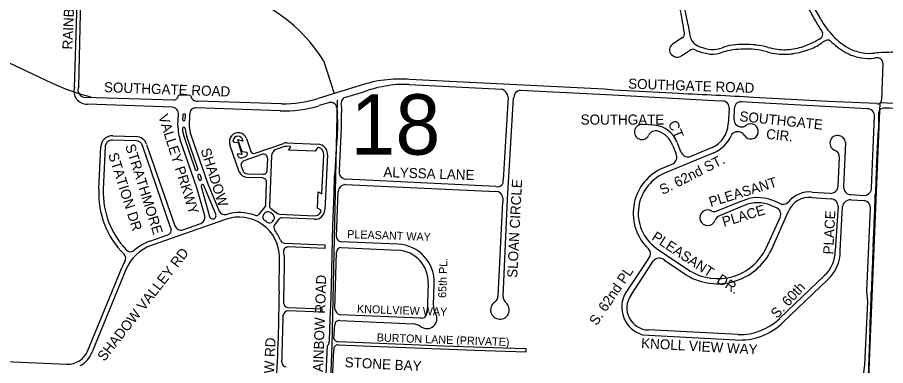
# Model space of a CAD drawing. Extents: x 0 to 712119, y 0 to 761125.
# Drawn here: x 660107 to 664425, y 718772 to 720502 of the extents above; entities that cross this region are included whole.
import ezdxf

# ---------------------------------------------------------------- set-up
doc = ezdxf.new("R2010")
doc.units = 0
for name, color, linetype in [('ISLANDS', 7, 'Continuous'), ('PAVED ROADS', 7, 'Continuous'), ('Priority 12', 7, 'Continuous'), ('Priority 16', 7, 'Continuous'), ('Priority 18', 7, 'Continuous'), ('street names', 7, 'Continuous')]:
    doc.layers.add(name, color=color, linetype=linetype)

msp = doc.modelspace()

# ---------------------------------------------------------------- linework, layer by layer
at = {"layer": 'ISLANDS'}
msp.add_lwpolyline([(664310.7, 717427.5), (664952, 717398.1), (665618, 717367.5), (665668.3, 718692.6), (665718.7, 720018.1), (664396.1, 720078.2), (664341, 718753), (664286, 717428.7)], close=True, dxfattribs=at)
at = {"layer": 'PAVED ROADS'}
for points in [[(660390.6, 720154.9), (660390.6, 720154.9), (660390.6, 720154.9), (660392.6, 720201.8), (660408.1, 720691.1), (660418.5, 721053.5), (660435.5, 721371.5), (660449, 721718), (660460.5, 721947)], [(660412.4, 720158.9), (660421.8, 720522), (660434.5, 720906.5), (660443.5, 721196), (660460.5, 721540), (660477.5, 721911.5)], [(663413.8, 720401.3), (663365.8, 720368.7)], [(664112.8, 720380.1), (664123.4, 720386.2)], [(664410.3, 720274.9), (664404.4, 720091.9)], [(661844.6, 720173.2), (661812.5, 720163.7), (661602.4, 720099.2)], [(662054.9, 720168.7), (662517.8, 720144.9)], [(663024.8, 720146.3), (662057.7, 720193.7)], [(661739.9, 720105.4), (661818, 720129.5), (661852.3, 720140.2)], [(662608.2, 720140.4), (663068.5, 720116.9), (663571.9, 720089.1), (663614.4, 720086.8)], [(663395.6, 720123.3), (663073, 720141.2), (663024.8, 720146.3)], [(660883.8, 720091.1), (660445.2, 720103.9)], [(660899, 720097.2), (660895.5, 720094.9)], [(660904.8, 720103.9), (660903.8, 720101.9)], [(660968.8, 720114.2), (660909, 720115.7), (660909, 720115.7)], [(660978, 720095.2), (660974.6, 720098.6)], [(660989.2, 720088.4), (660986.8, 720089.3)], [(661421.5, 720073.2), (661003.4, 720086.1)], [(661654.8, 720078), (661608, 720063.6)], [(661677.8, 720078.1), (661672.5, 720079.8)], [(662523.2, 719115.5), (662544.5, 719599), (662575.2, 720102.4)], [(662548, 720106.6), (662523.4, 719695.4)], [(664332.4, 720048.6), (663760.9, 720080.1), (663709.1, 720082.5)], [(664381.1, 720073.6), (664139.9, 720084), (663768.5, 720104.6)], [(660876.5, 720055.9), (660455.6, 720070.8)], [(660968.1, 720037.2), (660966.6, 720034.1)], [(660980.5, 720049.3), (660976.4, 720046.3)], [(661413.6, 720037.7), (660996.9, 720052.2)], [(661690.8, 720067.2), (661687.4, 720071)], [(663646.8, 720049.5), (663642.3, 719973.1)], [(663672.5, 720047.4), (663670.5, 719995.3)], [(665356.6, 720005.5), (664805, 720034.4), (664444.6, 720052), (664415.2, 720051.1)], [(660906, 719964.4), (660907.7, 720020.4), (660907.7, 720020.4)], [(660929.6, 720014.7), (660929.6, 720014.7), (660928.9, 719993.9)], [(660942.4, 719994.1), (660942.9, 720014.7)], [(660963.3, 720019.8), (660961.9, 719961.7)], [(661589.7, 717570.1), (661616.1, 718161.5), (661649.7, 718872.2), (661655.5, 718878.2), (661659.4, 718896.6), (661662.7, 719001.3), (661667.4, 719114.3), (661671.6, 719238.1), (661673.3, 719324.1), (661676.7, 719468), (661682, 719625.1), (661685, 719712), (661688, 719732.4), (661692.3, 719823.1), (661695.7, 719877.5), (661698.4, 719906.4), (661701.3, 719964.2), (661699.5, 720027.4)], [(661708.6, 719742.4), (661718.7, 719957.4), (661719.5, 720024.7)], [(664354.8, 719656.9), (664370.1, 720010.9)], [(660928.1, 719947.3), (660928.1, 719947.3)], [(660941.9, 719947.8), (660941.9, 719947.8)], [(663273.8, 719966.5), (663217.2, 719970.6)], [(660582.4, 719913), (660698.1, 719910.5)], [(660936.4, 719906.6), (660991.8, 719746.7)], [(661004.6, 719752), (660949.6, 719911)], [(660969.3, 719918.2), (661053.9, 719675.4), (661110.3, 719540.2)], [(660698, 719888.8), (660580, 719892.4)], [(660869.3, 719458.9), (660730.2, 719864.9)], [(660749.9, 719871.5), (660890.7, 719467.1)], [(661039.2, 719516.7), (660999.8, 719655.2), (660915.4, 719899.3)], [(661210.6, 719735.7), (661164.5, 719869.7)], [(661179.3, 719889.2), (661179.3, 719889.2)], [(661186.5, 719882.3), (661186.5, 719882.3), (661204.8, 719881), (661224, 719820.4), (661203.4, 719823.9)], [(661247.6, 719831.1), (661247.6, 719831.1), (661224.4, 719834.3), (661203.1, 719895), (661224.5, 719889.4)], [(661247.2, 719900.1), (661269, 719836.1), (661269, 719836.1)], [(661289.5, 719827.2), (661430.7, 719876.3)], [(661435.5, 719860.2), (661393, 719845.6)], [(661462, 719861.2), (661446.5, 719861.6)], [(661447.4, 719879.6), (661600.6, 719872.9)], [(663365.7, 719867.8), (663383, 719823.9)], [(663408.7, 719830.4), (663389.3, 719878.1)], [(664225.3, 719880.4), (664216.2, 719660.8)], [(660512.7, 719648.5), (660522.1, 719859)], [(660543.5, 719858.4), (660534, 719647.5)], [(661201.3, 719818.8), (661201.8, 719817.1)], [(661323.6, 719820.7), (661234, 719789)], [(661597.4, 719852.6), (661587.5, 719836.8), (661456.3, 719842.4), (661464.7, 719855.4)], [(661606.2, 719855), (661606.2, 719855)], [(661622, 719628.3), (661630.9, 719819.6)], [(661648.9, 719820.1), (661636.2, 719545.7)], [(661637.9, 719854.3), (661640.2, 719851.5)], [(661642.2, 719848.5), (661643, 719847.1), (661643, 719847.1)], [(663570.4, 719829.8), (663325.7, 719727.7)], [(663562.7, 719855.9), (663459.2, 719812.6)], [(661224.7, 719805), (661241.3, 719810.4)], [(661349, 719741.2), (661352, 719799.2)], [(661370.8, 719814), (661360.5, 719565.5), (661360.5, 719565.5)], [(663367.9, 719774.3), (663306.1, 719748)], [(664189.1, 719663.1), (664195.1, 719806.4)], [(661221.7, 719759.3), (661227.8, 719741.3)], [(661004, 719711.8), (661009.2, 719696.7)], [(661023.5, 719702.2), (661017.6, 719716.3)], [(661326.1, 719704.4), (661250.6, 719707)], [(661251.5, 719724.7), (661328.9, 719722.7)], [(662486, 719662.5), (661740.1, 719698.4)], [(661021.2, 719662.1), (661062.6, 719512.4), (661062.6, 719512.4)], [(661093.5, 719524.4), (661034.1, 719667.1), (661034.1, 719667.1)], [(661343.6, 719571.4), (661346.3, 719680.2)], [(661739.3, 719671.9), (662486.8, 719637.7)], [(661615, 719546.1), (661615, 719546.1), (661599.4, 719555.2), (661602.5, 719634.9), (661617.4, 719626.8)], [(661694.8, 719414), (661702.9, 719637.1)], [(662520.8, 719606.2), (662520.7, 719586.5), (662520.2, 719585.6)], [(663587.3, 719541.3), (663701.8, 719587.2), (663745.1, 719602.4)], [(664055.7, 719607.6), (664153.8, 719601.3)], [(664059.3, 719634.4), (664148.8, 719628.1)], [(664254.3, 719622.3), (664319.6, 719618.1)], [(661310.9, 719525.6), (661339.2, 719561.1)], [(662520.2, 719585.6), (662497.2, 719116.7)], [(663722.3, 719567.8), (663599.5, 719516.2)], [(663886.2, 719553.6), (663854.6, 719567.6)], [(664188.4, 719563.7), (664174.4, 719344.2)], [(664199.5, 719341.6), (664210.9, 719562.6)], [(664253.1, 719595.6), (664318.7, 719592.2)], [(661147.4, 719523.5), (661147.4, 719523.5)], [(661337.5, 719529.2), (661331.4, 719522.5), (661331.4, 719522.5)], [(661377.9, 719522.7), (661365.5, 719532.2)], [(661367.5, 719552.8), (661401.1, 719527.6)], [(661410.4, 719524.6), (661585.6, 719516.5), (661585.6, 719516.5)], [(663855.4, 719344.4), (663943.3, 719542.7)], [(664348.9, 719553.2), (664330.1, 719144.4), (664334.3, 719088.5), (664319.5, 718776.1), (664312.8, 718725.5), (664287.5, 718167.6)], [(661143, 719498.4), (660772, 719368.7)], [(660930.7, 719447.4), (661019.2, 719478.4)], [(661376.4, 719488.4), (661379.6, 719492.4)], [(661408, 719499), (661408, 719499), (661386.2, 719471.1)], [(661585.2, 719499), (661422.5, 719505.9)], [(663830.9, 719356.3), (663899.9, 719507.9)], [(660766.4, 719390.8), (660849.9, 719419.6)], [(662000, 719375.7), (661718.4, 719387.8)], [(661435.2, 719380.5), (661636, 719372.1), (661635.8, 719354.3), (661453.9, 719361.7)], [(661717.8, 719359.2), (661998.5, 719345.7)], [(663295.9, 719347.5), (663451.5, 719242.9)], [(661409.9, 719142.8), (661411, 719310.9)], [(661433.5, 719312.6), (661432.1, 719142.6)], [(661686.5, 719053), (661694.8, 719335.1)], [(663246.5, 719304.9), (663132.9, 719135.5)], [(660457.6, 718847.5), (660626.7, 719258.5)], [(663157.1, 719121), (663268.7, 719290.6)], [(663324.6, 719296.4), (663437.6, 719220.1)], [(660648.7, 719252.2), (660479.4, 718840)], [(664120.2, 719219.2), (663898.5, 719007.1)], [(662150.6, 719179.5), (662144.8, 719035.9)], [(662176.3, 719070.8), (662180.6, 719178.3)], [(663917.2, 718988.9), (664135.9, 719198)], [(661453.4, 719061.1), (661621.7, 719053.9), (661620.9, 719037.3), (661453.9, 719045)], [(662113.4, 719007.2), (661710, 719025.3)], [(661710.6, 718996.5), (662075.9, 718979)], [(661681.1, 718905.7), (661685.3, 718974.2)], [(663216.2, 718925.9), (663678.7, 718900)], [(663692.3, 718927), (663245.4, 718949.5)], [(664346.9, 718946.4), (664323.7, 718310.1), (664314.2, 718086.4), (664296.1, 717706.8), (664287.6, 717465.3)], [(661702.6, 718875.5), (661864.4, 718869.2), (662081.8, 718861.2), (662382, 718849.1), (662637.5, 718840.9), (662637.8, 718856.3), (662524.9, 718859.6), (662225.7, 718868.8), (662029.5, 718876.9), (661865.7, 718883.4), (661702.7, 718890.2)], [(661661.4, 718408.3), (661681.5, 718849.5)], [(659741.6, 718806.4), (660353.2, 718779.4), (660353.2, 718779.4)]]:
    msp.add_lwpolyline(points, dxfattribs=at)
for centre, radius, start, end in [((663055.1, 720449.2), 360.4, 6.4526, 24.6887), ((663024.3, 720440.3), 415.8, 6.9939, 23.9478), ((663550.1, 720225.6), 613.2, 25.9648, 33.2409), ((663190.1, 720033.2), 994.5, 26.8893, 31.1059), ((657787.2, 719437.8), 5723.6, 9.9393, 10.5907), ((665881.5, 720906.7), 2479.5, 189.652, 191.4721), ((664657, 720797.1), 659.5, 208.4469, 214.2209), ((664459.6, 720692.9), 409.6, 209.0367, 223.909), ((663399.2, 720422.6), 25.9, 304.3468, 6.8674), ((664088.7, 720418.6), 24.1, 304.2125, 18.4161), ((663521.3, 720424.2), 70.6, 188.684, 252.9568), ((663785.7, 720946.1), 632.5, 294.1605, 300.0391), ((663941.9, 720606.3), 283.5, 292.2907, 307.0678), ((664135.8, 720362.1), 27.1, 35.8016, 117.2036), ((664417.4, 720654.4), 352.5, 224.1462, 241.6938), ((663383.9, 720340.8), 33.3, 122.9738, 225.0488), ((672249.5, 706553.4), 16352.2, 122.52752, 122.74133), ((663468.1, 720323.3), 20.6, 60.4711, 123.3203), ((663531, 720428.9), 102.3, 239.0033, 247.0624), ((663584, 720577.1), 235.8, 249.2805, 263.5675), ((663563.1, 720495.8), 153.1, 267.9528, 288.7327), ((663693.2, 720145.7), 220.6, 97.8308, 111.5471), ((663785.7, 719671.8), 679.5, 100.2794, 104.6725), ((663724.6, 719801.1), 566.5, 84.4978, 96.2204), ((663729.4, 719847.6), 497, 84.7194, 97.5005), ((663723.6, 719937.5), 408.3, 74.1356, 82.7515), ((663724.2, 719920.5), 447.8, 74.9949, 82.9814), ((663949.3, 720775.5), 436.3, 255.5011, 261.8315), ((663918.4, 720578.9), 237.3, 262.4901, 281.5654), ((663883.5, 720807.7), 492.5, 279.3236, 289.6899), ((663923.6, 720640.3), 297, 278.1998, 294.0312), ((664431.5, 720682), 409.1, 228.0062, 241.4981), ((664370, 720638), 317.4, 247.834, 259.2476), ((663388.6, 720339.4), 35.9, 218.0931, 297.8543), ((663601.4, 720655.9), 339.6, 251.0537, 261.7379), ((663561.4, 720467), 147.5, 266.5809, 290.7559), ((663925.6, 720670), 351.5, 255.0968, 263.8236), ((663920.8, 720617), 298.3, 263.6491, 278.1848), ((664334.1, 720519.6), 220, 243.6115, 262.1742), ((664341.2, 720494.9), 196.7, 259.1526, 278.0871), ((664344.8, 720541.6), 218.2, 261.0429, 276.3244), ((664471.7, 719026.2), 1302.6, 90.2763, 94.5286), ((664383.6, 720202.2), 99, 87.0508, 98.5719), ((664386.6, 720277.3), 23.8, 354.1087, 84.9892), ((662091.8, 719333.4), 875.4, 103.708, 106.3986), ((662013.7, 719481.2), 714.5, 90.3208, 100.4292), ((662060, 719438.2), 732.9, 94.1451, 103.1401), ((662023.2, 719464.3), 705.2, 87.4248, 91.318), ((662011.6, 719648.7), 547, 85.1705, 90.2035), ((660453.8, 720136.6), 65.8, 163.8776, 271.58), ((660446.7, 720142.1), 38.2, 154.0341, 267.7916), ((668486.4, 697129.1), 23948.4, 105.98011, 106.0824), ((662493.3, 720094.6), 56, 12.3794, 63.9944), ((662613, 720103), 37.7, 97.3083, 180.8737), ((662175.1, 692110), 28039.9, 86.7424, 87.50532), ((660883.9, 720110.8), 19.7, 269.7904, 306.1077), ((660892.8, 720108.3), 12.7, 299.0835, 329.5808), ((660869.6, 720122.8), 40, 331.7245, 349.7402), ((661004.2, 720118.7), 35.7, 187.2193, 214.1323), ((660998.6, 720116.4), 29.6, 225.8703, 246.354), ((661004, 720134.4), 48.3, 252.1615, 269.2795), ((661432.1, 720642.5), 569.4, 268.9319, 287.4099), ((661667.1, 720044.8), 35.4, 81.1863, 110.1989), ((661654.7, 720037.3), 46.9, 45.9057, 60.5014), ((661748.9, 720073.9), 32.8, 106.0052, 207.633), ((663613.7, 720053.5), 33.3, 353.1346, 88.7973), ((663705, 720050.1), 32.7, 82.8546, 184.7737), ((664386.1, 720091.2), 18.2, 254.1185, 2.1814), ((660875.6, 720023.6), 32.3, 354.1778, 88.4785), ((661027.6, 720012.9), 64.7, 160.8501, 173.8973), ((660993.8, 720022), 29.9, 125.4618, 149.3521), ((660993.5, 720022.9), 29.5, 83.3105, 116.2355), ((661431.3, 720646.6), 609.2, 268.331, 286.8593), ((661670.2, 720053.2), 24.9, 4.6446, 34.1507), ((661872.7, 720069.3), 178.2, 184.5246, 193.5795), ((661606.6, 720043), 114.4, 350.8119, 7.9078), ((664333.4, 720011.9), 36.7, 358.4333, 91.5505), ((664413.2, 720028.7), 22.5, 84.9182, 172.9814), ((660935.7, 719994.4), 6.8, 184.4985, 356.7796), ((660936.2, 720016.5), 6.91, 345.6664, 194.8437), ((663706, 719994.5), 35.5, 178.6122, 263.2897), ((662540.6, 720008), 1850.4, 359.2662, 0.7272), ((661088.8, 719957.6), 183, 177.852, 198.5736), ((660934.9, 719949.7), 7.2, 345.4449, 198.7922), ((661083.8, 719957.7), 156, 183.8221, 199.1371), ((661070.8, 719955.5), 129.1, 183.4201, 200.1612), ((661122.8, 719966.7), 161, 181.78, 197.5338), ((663213.1, 719933.2), 37.6, 83.6367, 331.7371), ((663263, 719832.8), 134.2, 19.7563, 85.4143), ((663509.2, 719977.9), 133.2, 293.6839, 357.9287), ((663710.4, 719990.4), 32.4, 254.7223, 310.9759), ((663753.9, 719935.7), 37.6, 213.5742, 126.3171), ((664978.9, 719928.4), 590.7, 174.5721, 179.8447), ((660577.2, 719858.2), 55.1, 84.4857, 179.1479), ((660696.8, 719854.9), 55.6, 17.4118, 88.6914), ((661205.7, 719885.4), 44, 19.5715, 200.8091), ((661204.4, 719886.5), 25.2, 9.4339, 173.896), ((663281.3, 719900.2), 38.3, 71.1248, 156.6212), ((663260.4, 719829.6), 111.9, 19.9339, 72.6894), ((663504.5, 719983.1), 166.8, 293.2597, 335.7177), ((663686.3, 719901.2), 32.6, 100.962, 155.8168), ((663688.4, 719894.3), 39.7, 68.5323, 102.0939), ((663694.6, 719901.3), 31.2, 25.9556, 74.372), ((664186.7, 719877.5), 38.7, 4.3374, 251.0176), ((660878.8, 720059.2), 3511.8, 356.487, 357.8915), ((660577.5, 719858.4), 34, 85.7683, 179.9646), ((660698.4, 719855.6), 33.1, 16.2249, 90.7037), ((661187.4, 719890.4), 8.14, 188.1167, 263.8579), ((661226.3, 719892.2), 3.4, 237.7953, 332.3592), ((661446.9, 719838.6), 41, 89.3142, 113.2666), ((661443.9, 719838.3), 23.4, 83.6385, 111.1039), ((661461.9, 719857.6), 3.61, 321.9582, 88.574), ((661598.6, 719822.2), 50.8, 39.2256, 87.7372), ((661204.5, 719820.5), 3.6, 108.968, 206.9177), ((661219.9, 719823.6), 19.2, 199.6791, 284.6049), ((661236.4, 719824.6), 15, 289.1371, 353.4271), ((661245.7, 719825.3), 6.09, 337.007, 71.9773), ((661283.5, 719841.5), 15.5, 200.4409, 292.597), ((661330.9, 719800.9), 21.2, 355.4808, 110.2056), ((661404.7, 719813.8), 33.9, 110.175, 179.6876), ((661603.1, 719848.7), 7.01, 64.5293, 145.4205), ((661597.4, 719822.5), 33.7, 355.145, 74.8387), ((661624, 719838.3), 20.9, 29.2379, 38.985), ((661606.6, 719824.9), 42.6, 353.5577, 31.4401), ((663348.2, 719807.4), 38.5, 300.7091, 25.4787), ((663443.1, 719847.3), 38.3, 206.1133, 294.9253), ((664163, 719810.6), 32.4, 352.6272, 69.7853), ((659904, 720031.9), 4483.9, 356.4505, 357.599), ((661239.8, 719769.2), 20.7, 106.3599, 208.7629), ((660998, 719749.8), 6.9, 206.1996, 19.1289), ((661252.9, 719752.4), 45.5, 201.5413, 267.0241), ((661254, 719753.6), 28.9, 205.0056, 264.9792), ((661329.8, 719741.9), 19.2, 267.5167, 357.8864), ((661741.8, 719733), 34.6, 164.2045, 267.1282), ((663413.2, 719529.1), 243.7, 116.0858, 226.6734), ((671186.7, 719398.1), 6816.7, 177.0047, 178.12654), ((661010.7, 719714.2), 7.17, 16.8751, 200.1379), ((661015.9, 719700.7), 7.76, 210.9957, 11.6388), ((661326.4, 719684.1), 20.3, 349.0913, 90.6398), ((662495, 719690), 28.9, 251.8607, 10.8108), ((663409.7, 719529.9), 214.9, 113.0135, 238.041), ((660930.6, 719625.5), 418.5, 176.8537, 225.5716), ((660949.8, 719634.4), 416, 178.2006, 223.2138), ((661027.6, 719664.9), 6.91, 18.7315, 203.9135), ((661740.1, 719634.7), 37.3, 91.1319, 176.2561), ((664150.2, 719667.2), 39.2, 267.9722, 353.9941), ((664251.8, 719658), 35.8, 175.4211, 274.0277), ((664318.9, 719654.1), 36, 271.1903, 4.3909), ((661619.2, 719629.2), 2.97, 233.1799, 344.0262), ((662487, 719603.8), 33.9, 3.9491, 90.3172), ((663788.7, 719390.7), 216.1, 60.5877, 101.6359), ((664046.8, 719497.5), 137.5, 84.8155, 139.7333), ((664045.2, 719496.1), 112, 84.6011, 155.4312), ((664151.2, 719564.2), 37.2, 359.1933, 85.876), ((648439.1, 720142.2), 15943.1, 357.64675, 358.12643), ((661324.8, 719573.4), 18.9, 319.5261, 353.896), ((661376.2, 719565.9), 15.7, 181.4551, 236.3815), ((663788.3, 719412), 169.1, 66.9085, 112.9495), ((663914, 719610.5), 37, 238.6699, 319.0904), ((664248.8, 719557.6), 38.2, 83.5392, 172.5281), ((664313.3, 719556.8), 35.8, 354.1378, 81.3203), ((661008.6, 719508.3), 31.8, 289.5423, 15.3057), ((661078.5, 719517.4), 16.6, 197.6355, 25.0977), ((661138.1, 719552.4), 30.3, 203.7132, 287.9624), ((661210.5, 719308.6), 224, 69.9219, 106.3555), ((661295.2, 719536.2), 18.9, 245.6628, 325.7891), ((661347.9, 719510.5), 20.4, 144.0509, 241.2947), ((661353.3, 719514.7), 21.4, 55.0919, 137.4568), ((661364.9, 719506.7), 20.6, 315.8141, 50.7631), ((661412.5, 719547.2), 22.7, 239.7826, 264.6042), ((661587.1, 719548.2), 49.2, 267.8228, 357.0524), ((661587, 719548.6), 32.1, 267.4399, 336.6653), ((661608, 719539.9), 9.4, 334.6384, 41.3266), ((663540.1, 719507.1), 39, 57.7236, 341.7343), ((663572.6, 719571.6), 33.6, 249.6367, 295.826), ((663610.9, 719481.8), 36.2, 108.3436, 158.9146), ((663870, 719523.8), 33.9, 331.885, 61.4238), ((661210.2, 719309.2), 200.8, 0.468, 109.5542), ((661210.5, 719308.6), 224, 51.995, 55.2852), ((661360.8, 719500.8), 20, 231.995, 321.5055), ((661420, 719492.5), 13.6, 79.4276, 151.6775), ((639854.6, 720581.3), 24538.5, 357.14712, 357.44529), ((660845.6, 719446.2), 26.9, 279.3396, 28.2286), ((660920.3, 719476.7), 31.1, 198.0142, 289.5554), ((661402.8, 719459.3), 20.4, 144.4757, 224.2708), ((661145.7, 719275.3), 295.9, 23.2174, 34.9905), ((660852.6, 719153.5), 252.5, 109.979, 130.4311), ((661435.4, 719400), 19.5, 204.3238, 269.2809), ((661717.8, 719411), 23.2, 172.3734, 271.4941), ((660669.5, 719366.6), 28.5, 216.694, 312.9678), ((660847.6, 719165.3), 217.1, 110.3866, 156.3818), ((661452.3, 719339.7), 22, 85.7446, 187.5864), ((661719.5, 719334.5), 24.8, 93.933, 178.6407), ((661990.7, 719185.9), 160, 357.7066, 87.2056), ((661990.7, 719185.9), 190, 357.7066, 87.2056), ((663222.5, 719328.1), 33.4, 316.0184, 45.2633), ((663588.7, 719476.6), 297.8, 239.5152, 333.636), ((663589.9, 719471.1), 267, 238.7573, 334.524), ((664012.7, 719340.1), 161.7, 311.6364, 1.4647), ((678483.5, 718656.3), 14138.4, 177.14716, 177.66465), ((660616, 719305.3), 30.4, 327.1699, 44.7188), ((661583.7, 719343.9), 153.4, 182.6443, 191.7709), ((663299.4, 719267.2), 38.6, 49.268, 142.6975), ((664005.3, 719341.8), 194.2, 312.2571, 359.9505), ((660892.6, 719147.4), 288.2, 150.6083, 157.3182), ((673225.1, 718896.9), 8874.6, 177.83318, 178.43845), ((651959, 719221.1), 9451.3, 356.69903, 359.52532), ((656847.7, 719115.4), 4584.5, 359.5642, 0.3399), ((663255.3, 719062.8), 142.4, 149.2674, 254.0583), ((655418.3, 719382.3), 8938.9, 357.8376, 358.43851), ((662507, 719049.3), 46.5, 123.9835, 50.4151), ((662460.3, 719118.5), 37, 303.9835, 357.1993), ((662560.2, 719113.6), 37, 177.1994, 230.4151), ((663247.7, 719059.1), 109.7, 145.647, 268.8324), ((661453.9, 719020.5), 24.5, 89.9559, 175.7189), ((661452.6, 719081.7), 20.6, 183.3144, 272.2159), ((661725.2, 719062.1), 39.8, 193.2053, 247.4088), ((662246.2, 719068), 70, 177.7066, 211.2639), ((615939, 720949), 48449.2, 357.63112, 357.74778), ((650833.6, 719238.3), 10598, 357.56844, 358.83211), ((661708.8, 718973), 23.6, 85.7529, 176.9774), ((662114.9, 719037.1), 30, 267.1914, 357.7066), ((662143.6, 719005.7), 50, 233.6341, 31.2639), ((663701.4, 719209.1), 282.3, 268.1502, 314.3087), ((662072.5, 718909.1), 70, 53.6341, 87.1914), ((663700.4, 719206.1), 306.8, 265.9361, 314.9497), ((661702.5, 718854), 21.4, 89.7332, 192.1341), ((661703.4, 718914), 23.8, 200.3665, 268.3012), ((660358.1, 718886), 106.7, 267.4057, 338.8415), ((660352.9, 718891.2), 136.5, 299.2719, 337.9651), ((661444.7, 718788.8), 22.6, 180.1523, 266.6466)]:
    msp.add_arc(centre, radius, start, end, dxfattribs=at)
at = {"layer": 'Priority 12'}
msp.add_lwpolyline([(659125.9, 720721.7), (660280.2, 720176.1)], dxfattribs=at)
msp.add_arc((660707.5, 721080.2), 1000, 244.701, 256.4077, dxfattribs=at)
at = {"layer": 'Priority 16'}
msp.add_lwpolyline([(661629.1, 720288.2), (661682.5, 720123.8)], dxfattribs=at)
msp.add_arc((660956.4, 719866.5), 794, 32.085, 64.8332, dxfattribs=at)
at = {"layer": 'Priority 18'}
msp.add_lwpolyline([(661697.4, 720091.7), (661670.9, 718874.5), (661622.1, 717551.1), (661558.5, 716237.1), (661495, 714923.1), (661434.7, 713608.9), (661373.4, 712274)], dxfattribs=at)

# ---------------------------------------------------------------- texts
msp.add_text('18', height=300, dxfattribs=at).set_placement((661764.2, 719820.1))
at = {"layer": 'street names'}
for s, height, rotation, p in [('RAINBOW ROAD', 50, 87.7183, (660380.9, 720341.8)), ('SOUTHGATE ROAD', 50, 357.9838, (660537.4, 720130.9)), ('SOUTHGATE ROAD', 50, 357.9838, (663143.9, 720148.6)), ('SOUTHGATE', 50, 354.0898, (663696.3, 719986.8)), ('VALLEY PRKWY', 50, 287.6639, (660807.2, 720011.6)), ('SOUTHGATE', 50, 0.0105, (662908.4, 719969.5)), ('CT.', 50, 292.9564, (663341.8, 719977.2)), ('CIR.', 50, 354.0898, (663828.9, 719899)), ('STRATHMORE', 50, 287.6639, (660642.6, 719864.1)), ('STATION DR', 50, 287.6639, (660558.4, 719821.4)), ('SHADOW ', 50, 287.6639, (661018, 719844)), ('S. 62nd ST.', 50, 27.0105, (663316, 719619.3)), ('ALYSSA LANE', 50, 358.1213, (661926.5, 719708.9)), ('SLOAN CIRCLE', 50, 87.1213, (662592.8, 719207.4)), ('PLEASANT', 50, 17.0105, (663555, 719560)), ('PLACE', 50, 17.0105, (663621.2, 719460.9)), ('PLACE', 50, 87.0105, (664164, 719323.4)), ('PLEASANT WAY', 40, 357.9838, (661746.7, 719406.1)), ('PLEASANT  DR.', 50, 326.7667, (663257.6, 719400.3)), ('SHADOW VALLEY RD', 50, 52.0327, (660539.8, 718790.1)), ('65th PL.', 40, 88.0489, (662239.4, 719108)), ('SOUTH RAINBOW ROAD', 50, 88.0489, (661617, 718439.2)), ('S. 62nd PL', 50, 56.1355, (662988.3, 718967.9)), ('S. 60th', 50, 47.0105, (663885, 719003.2)), ('KNOLLVIEW WAY', 40, 357.9838, (661795.6, 719035)), ('BURTON LANE (PRIVATE)', 40, 357.9838, (661894, 718892.6)), ('VALLEY VIEW RD', 50, 87.3557, (661365.9, 718353.6)), ('KNOLL VIEW WAY', 50, 356.7422, (663208.1, 718859.6)), ('STONE BAY', 50, 357.0105, (661733.8, 718764.6))]:
    msp.add_text(s, height=height, rotation=rotation, dxfattribs=at).set_placement(p)

doc.saveas('drawing.dxf')
